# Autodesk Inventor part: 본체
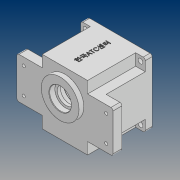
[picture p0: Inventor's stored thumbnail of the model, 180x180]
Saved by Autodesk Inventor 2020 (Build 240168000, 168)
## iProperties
Created: 2020-07
Part Number: 본체
Material: 일반
Document SubType Name: Modeling
Designer: PC312-
Density: 1 g/cm^3
Appearance: 기본값
Author: PC312-
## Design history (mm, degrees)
sketch "스케치1"
  geometry: L1 (33, -47)-(-33, -47); L2 (-33, 47)-(33, 47); L3 (33, -47)-(-33, 47); L4 (-33, -47)-(33, 47); L5 (70, -30)-(70, 30); L6 (-70, 30)-(-70, -30); L7 (-70, -30)-(70, 30); L8 (70, -30)-(-70, 30); L9 (70, 30)-(33, 30); L10 (-33, 30)-(-70, 30); L11 (-33, -47)-(-33, -30); L12 (-33, 30)-(-33, 47); L13 (-70, -30)-(-33, -30); L14 (33, -30)-(70, -30); L15 (33, 47)-(33, 30); L16 (33, -30)-(33, -47); 1 further point
  constraints: 32 end point, 10 parallel, 4 midpoint, 4 perpendicular, 3 horizontal
  dimensions: "d0" = 66 distance of L2.start L2.end; "d1" = 94 distance of L2.end L1.start; "d2" = 140 distance of L5.end L6.start; "d3" = 60 distance of L6.start L6.end; "d4" = 33 distance from line of point (0, 0) L15; "d5" = 30 distance from line of point (0, 0) L9; "d6" = 47 distance from line of point (0, 0) L1; "d7" = 70 distance from line of point (0, 0) L6
extrude "돌출1" new body sketch "스케치1" distance "d8" = 13; taper "d9" = 0 deg
sketch "스케치2"
  geometry: L1 (-47, -47)-(47, -47); L2 (47, -47)-(47, 47); L3 (47, 47)-(-47, 47); L4 (-47, 47)-(-47, -47); L5 (-47, -47)-(47, 47); L6 (47, -47)-(-47, 47); 1 further point
  constraints: 12 end point, 2 midpoint, 2 parallel, 1 horizontal, 1 perpendicular
  dimensions: "d10" = 94 distance of L3.end L2.end; "d11" = 94 distance of L2.end L1.end
extrude "돌출2" join sketch "스케치2" distance "d12" = 67; taper "d13" = 0 deg
sketch "스케치3"
  geometry: L1 (33, 30)-(47, 30) reference; L2 (47, 47)-(47, 30) reference; L3 (33, 47)-(47, 47) reference; L4 (33, 47)-(33, 30) reference; L5 (-33, 30)-(-33, 47) reference; L6 (-47, 47)-(-33, 47) reference; L7 (-47, 30)-(-47, 47) reference; L8 (-47, 30)-(-33, 30) reference; L9 (-33, -47)-(-33, -30) reference; L10 (-33, -30)-(-47, -30) reference; L11 (-47, -47)-(-47, -30) reference; L12 (-33, -47)-(-47, -47) reference; L13 (47, -30)-(33, -30) reference; L14 (33, -30)-(33, -47) reference; L15 (47, -47)-(33, -47) reference; L16 (47, -30)-(47, -47) reference; 1 further point
extrude "돌출3" cut sketch "스케치3" distance "d14" = 57; taper "d15" = 0 deg
sketch "스케치4"
  geometry: C1 r 27.5 at (0, 11); 1 further point
  constraints: 1 centre point, 1 vertical alignment
  dimensions: "d16" = 55 diameter of C1; "d17" = 11 distance of point (0, 0) C1.centre
extrude "돌출4" join sketch "스케치4" distance "d18" = 7; taper "d19" = 0 deg
sketch "스케치5"
  geometry: C1 r 27.5 at (0, 0) reference; C2 r 16 at (0, 0); 1 further point
  constraints: 1 centre point, 1 coincident
  dimensions: "d20" = 32 diameter of C2
extrude "돌출5" cut sketch "스케치5" distance "d21" = 8.3; taper "d22" = 0 deg
sketch "스케치6"
  geometry: C1 r 16 at (0, 0) reference; C2 r 12.5 at (0, 0); 1 further point
  constraints: 1 centre point, 1 coincident
  dimensions: "d23" = 25 diameter of C2
sketch "스케치7"
  geometry: C1 r 43 at (0, 0); 1 further point
  constraints: 1 centre point, 1 coincident
  dimensions: "d24" = 86 diameter of C1
extrude "돌출6" cut sketch "스케치7" distance "d25" = 9; taper "d26" = 0 deg
sketch "스케치8"
  geometry: C1 r 40 at (0, 0); 1 further point
  constraints: 1 centre point, 1 coincident
  dimensions: "d27" = 80 diameter of C1
extrude "돌출7" cut sketch "스케치8" distance "d28" = 62; taper "d29" = 0 deg
extrude "돌출8" cut sketch "스케치6" distance "d30" = 4.7; taper "d31" = 0 deg
sketch "스케치9"
  geometry: C1 r 27.5 at (0, 0) reference; C2 r 17.5 at (0, 0); 1 further point
  constraints: 1 centre point, 1 coincident
  dimensions: "d32" = 35 diameter of C2
extrude "돌출9" cut sketch "스케치9" distance "d33" = 10; taper "d34" = 0 deg
sketch "스케치12"
  geometry: C1 r 17.5 at (0, 11) reference; C2 r 11 at (0, -20) reference; A1 r 21 centre (0, 11) between (8.978, -7.984) and (-8.978, -7.984); A2 r 15 centre (0, -20) between (-8.978, -7.984) and (8.978, -7.984); 1 further point
  constraints: 4 point on circle, 2 centre point, 2 coincident
  dimensions: "d42" = 42 diameter of A1; "d43" = 30 diameter of A2
extrude "돌출12" join sketch "스케치12" distance "d44" = 7; taper "d45" = 0 deg
sketch "스케치13"
  geometry: A1 r 36 centre (0, 0) between (-36, 0) and (-35.778, -3.995); A2 r 4 centre (-36, 0) between (-35.852, -3.997) and (-35.852, 3.997); A3 r 3.5 centre (-35.722, -7.495) between (-35.778, -3.995) and (-39.148, -8.214); A4 r 3.5 centre (-35.722, 7.495) between (-39.148, 8.214) and (-35.778, 3.995); A5 r 40 centre (0, 0) between (-39.148, -8.214) and (-39.148, 8.214) reference; 1 further point
  constraints: 13 point on circle, 4 centre point, 4 tangent, 1 coincident, 1 horizontal alignment
  dimensions: "d46" = 72 diameter of A1; "d47" = 8 diameter of A2; "d48" = 7 diameter of A3; "d49" = 7 diameter of A4
extrude "돌출13" join sketch "스케치13" stored distance "d50" = 7; taper "d51" = 0 deg
sketch "스케치14"
  geometry: A1 r 4 centre (-36, 0) between (-35.852, -3.997) and (-35.852, 3.997) reference; 2 further points
  constraints: 1 coincident
hole "구멍1" sketch "스케치14" at (-36, 0) diameter "d52" = 3.242; stored, may be unused: countersink angle "d56" = 90 deg, drill point angle "d58" = 118 deg; dims "d53" = 7, "d54" = 4, "d55" = 2, "d57" = 9
sketch "스케치15"
  geometry: C1 r 11 at (0, 0) reference; C2 r 9.5 at (0, 0); 1 further point
  constraints: 1 centre point, 1 coincident
  dimensions: "d59" = 19 diameter of C2
extrude "돌출14" cut sketch "스케치15" distance "d60" = 3; taper "d61" = 0 deg
sketch "스케치16"
  geometry: L1 (-47, 30)-(-70, 30) reference; L2 (-70, 30)-(-70, -30) reference; L3 (-70, -30)-(-47, -30) reference; 2 further points
  dimensions: "d62" = 11 distance from line of L1 point (-60, 19); "d63" = 10 distance from line of L2 point (-60, 19)
hole "구멍2" sketch "스케치16" at (-60, 19) diameter "d66" = 4.5; stored, may be unused: countersink angle "d70" = 90 deg, drill point angle "d72" = 118 deg; dims "d67" = 7, "d68" = 10, "d69" = 5, "d71" = 9
sketch "스케치17"
  geometry: L1 (47, 47)-(47, 30) reference; L2 (70, 30)-(33, 30) reference; 2 further points
  dimensions: "d79" = 7 distance from line of L1 point (40, 40); "d80" = 10 distance from line of L2 point (40, 40)
hole "구멍3" sketch "스케치17" at (40, 40) diameter "d81" = 7; stored, may be unused: countersink angle "d85" = 90 deg, drill point angle "d87" = 118 deg; dims "d82" = 7, "d83" = 10, "d84" = 5, "d86" = 9
fillet "모깎기1" dims "d94" = 3
chamfer "모따기1" distance "d95" = 1; stored, may be unused: second distance "d96" = 2, angle "d97" = 45 deg
fillet "모깎기3" dims "d99" = 3
chamfer "모따기2" distance "d100" = 0.8; stored, may be unused: second distance "d101" = 2, angle "d102" = 30 deg
fillet "모깎기4" dims "d103" = 3
chamfer "모따기3" distance "d104" = 1; stored, may be unused: second distance "d105" = 2, angle "d106" = 30 deg
node "작업 평면1"
sketch "스케치18"
  geometry: L1 (-11, 80)-(77, 80) reference; 2 further points
  constraints: 1 vertical alignment, 1 other
  dimensions: "d108" = 40 distance from line of L1 point (33, 40)
feature "엠보싱1" sketch "스케치18" dims "d0" = 66, "d1" = 94, "d2" = 140, "d3" = 60, "d4" = 33, "d5" = 30, "d6" = 47, "d7" = 70, "d10" = 94, "d11" = 94, "d109" = 0.5, "d110" = 0
node "솔리드1"
mirror "미러1"
pattern_linear "직사각형 패턴1" dims "d75" = 38, "d78" = 120
pattern_linear "직사각형 패턴2" dims "d90" = 80, "d93" = 80
node "투영된 루프1"
node "투영된 루프2"
node "투영된 루프3"
node "투영된 루프4"
feature "A9D066F2-1C7D-4E18-AEED-F7BC21143FA4" dims "d66" = 4.5, "d67" = 7, "d68" = 10, "d69" = 5, "d70" = 90 deg, "d71" = 9, "d72" = 118 deg
